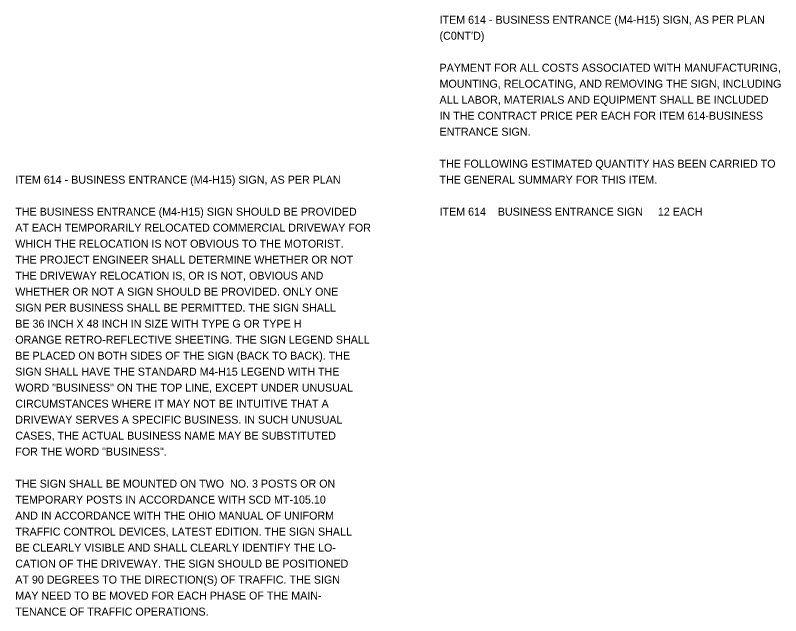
# Model space of a CAD drawing. Extents: x -10.9 to 54.4, y -2.9 to 34.3.
# Drawn here: x 10.32 to 23.71, y 23.8 to 34.31 of the extents above; entities that cross this region are included whole.
import ezdxf

# ---------------------------------------------------------------- set-up
doc = ezdxf.new("R2010")
doc.units = 0
doc.layers.add('SH_Text', color=7, linetype='Continuous')

msp = doc.modelspace()

# ---------------------------------------------------------------- texts
at = {"layer": 'SH_Text'}
for s, p in [('ITEM 614 - BUSINESS ENTRANCE (M4-H15) SIGN, AS PER PLAN', (17.74, 34.164)), ("(C0NT'D)", (17.74, 33.884)), ('PAYMENT FOR ALL COSTS ASSOCIATED WITH MANUFACTURING,', (17.74, 33.324)), ('MOUNTING, RELOCATING, AND REMOVING THE SIGN, INCLUDING', (17.74, 33.044)), ('ALL LABOR, MATERIALS AND EQUIPMENT SHALL BE INCLUDED', (17.74, 32.764)), ('IN THE CONTRACT PRICE PER EACH FOR ITEM 614-BUSINESS', (17.74, 32.484)), ('ENTRANCE SIGN.', (17.74, 32.204)), ('THE FOLLOWING ESTIMATED QUANTITY HAS BEEN CARRIED TO', (17.74, 31.644)), ('ITEM 614 - BUSINESS ENTRANCE (M4-H15) SIGN, AS PER PLAN', (10.32, 31.364)), ('THE GENERAL SUMMARY FOR THIS ITEM.', (17.74, 31.364)), ('THE BUSINESS ENTRANCE (M4-H15) SIGN SHOULD BE PROVIDED', (10.32, 30.804)), ('ITEM 614    BUSINESS ENTRANCE SIGN     12 EACH', (17.74, 30.804)), ('AT EACH TEMPORARILY RELOCATED COMMERCIAL DRIVEWAY FOR', (10.32, 30.524)), ('WHICH THE RELOCATION IS NOT OBVIOUS TO THE MOTORIST.', (10.32, 30.244)), ('THE PROJECT ENGINEER SHALL DETERMINE WHETHER OR NOT', (10.32, 29.964)), ('THE DRIVEWAY RELOCATION IS, OR IS NOT, OBVIOUS AND', (10.32, 29.684)), ('WHETHER OR NOT A SIGN SHOULD BE PROVIDED. ONLY ONE', (10.32, 29.404)), ('SIGN PER BUSINESS SHALL BE PERMITTED. THE SIGN SHALL', (10.32, 29.124)), ('BE 36 INCH X 48 INCH IN SIZE WITH TYPE G OR TYPE H', (10.32, 28.844)), ('ORANGE RETRO-REFLECTIVE SHEETING. THE SIGN LEGEND SHALL', (10.32, 28.564)), ('BE PLACED ON BOTH SIDES OF THE SIGN (BACK TO BACK). THE', (10.32, 28.284)), ('SIGN SHALL HAVE THE STANDARD M4-H15 LEGEND WITH THE', (10.32, 28.004)), ('WORD "BUSINESS" ON THE TOP LINE, EXCEPT UNDER UNUSUAL', (10.32, 27.724)), ('CIRCUMSTANCES WHERE IT MAY NOT BE INTUITIVE THAT A', (10.32, 27.444)), ('DRIVEWAY SERVES A SPECIFIC BUSINESS. IN SUCH UNUSUAL', (10.32, 27.164)), ('CASES, THE ACTUAL BUSINESS NAME MAY BE SUBSTITUTED', (10.32, 26.884)), ('FOR THE WORD "BUSINESS".', (10.32, 26.604)), ('THE SIGN SHALL BE MOUNTED ON TWO  NO. 3 POSTS OR ON', (10.32, 26.044)), ('TEMPORARY POSTS IN ACCORDANCE WITH SCD MT-105.10', (10.32, 25.764)), ('AND IN ACCORDANCE WITH THE OHIO MANUAL OF UNIFORM', (10.32, 25.484)), ('TRAFFIC CONTROL DEVICES, LATEST EDITION. THE SIGN SHALL', (10.32, 25.204)), ('BE CLEARLY VISIBLE AND SHALL CLEARLY IDENTIFY THE LO-', (10.32, 24.924)), ('CATION OF THE DRIVEWAY. THE SIGN SHOULD BE POSITIONED', (10.32, 24.644)), ('AT 90 DEGREES TO THE DIRECTION(S) OF TRAFFIC. THE SIGN', (10.32, 24.364)), ('MAY NEED TO BE MOVED FOR EACH PHASE OF THE MAIN-', (10.32, 24.084)), ('TENANCE OF TRAFFIC OPERATIONS.', (10.32, 23.804))]:
    msp.add_text(s, height=0.14, dxfattribs=at).set_placement(p)

doc.saveas('drawing.dxf')
